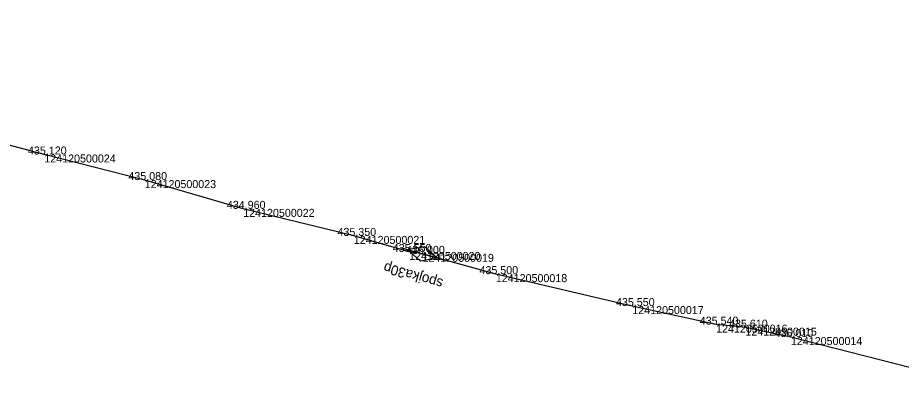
# Model space of a CAD drawing. Extents: x -637342 to -635997, y -1153616 to -1153154.
# Drawn here: x -637005.8 to -636873.3, y -1153373.9 to -1153318.4 of the extents above; entities that cross this region are included whole.
import ezdxf

# ---------------------------------------------------------------- set-up
doc = ezdxf.new("R2010")
doc.units = 0
for name, color, linetype in [('Vrstva 28', 7, 'Continuous'), ('Vrstva 60', 7, 'Continuous'), ('Vrstva 61', 7, 'Continuous')]:
    doc.layers.add(name, color=color, linetype=linetype)

msp = doc.modelspace()

# ---------------------------------------------------------------- linework, layer by layer
at = {"layer": 'Vrstva 28'}
for p, q in [((-636947.36, -1153353.23), (-636944.81, -1153352.76)), ((-636944.81, -1153352.76), (-636942.9, -1153354.53)), ((-636948.48, -1153352.91), (-636941.78, -1153354.85)), ((-636945.45, -1153355), (-636947.36, -1153353.23)), ((-636942.9, -1153354.53), (-636945.45, -1153355))]:
    msp.add_line(p, q, dxfattribs=at)
msp.add_lwpolyline([(-636859.31, -1153373.92), (-636867.59, -1153372.08), (-636889.87, -1153366.37), (-636896.7, -1153364.96), (-636901.09, -1153364.51), (-636913.66, -1153361.72), (-636934.13, -1153356.93), (-636945.13, -1153353.88), (-636947.14, -1153353.6), (-636955.43, -1153351.19), (-636972.02, -1153347.13), (-636986.79, -1153342.81), (-637001.85, -1153338.97), (-637018.07, -1153334.65), (-637042.74, -1153328.68), (-637062.52, -1153323.84), (-637073.89, -1153320.08), (-637082.06, -1153319.38), (-637087.31, -1153318.43)], dxfattribs=at)
at = {"layer": 'Vrstva 60'}
for p, q in [((-637001.85, -1153338.97), (-637001.85, -1153338.97)), ((-636986.79, -1153342.81), (-636986.79, -1153342.81)), ((-636972.02, -1153347.13), (-636972.02, -1153347.13)), ((-636955.43, -1153351.19), (-636955.43, -1153351.19)), ((-636947.14, -1153353.6), (-636947.14, -1153353.6)), ((-636945.13, -1153353.88), (-636945.13, -1153353.88)), ((-636934.13, -1153356.93), (-636934.13, -1153356.93)), ((-636913.66, -1153361.72), (-636913.66, -1153361.72)), ((-636901.09, -1153364.51), (-636901.09, -1153364.51)), ((-636896.7, -1153364.96), (-636896.7, -1153364.96)), ((-636889.87, -1153366.37), (-636889.87, -1153366.37))]:
    msp.add_line(p, q, dxfattribs=at)

# ---------------------------------------------------------------- texts
at = {"layer": 'Vrstva 28'}
msp.add_text('spojka30p', height=1.5, rotation=163.7902, dxfattribs=at).set_placement((-636941.93, -1153357.74))
at = {"layer": 'Vrstva 60'}
for s, p in [('124120500024', (-637001.85, -1153340.17)), ('124120500023', (-636986.79, -1153344.01)), ('124120500022', (-636972.02, -1153348.33)), ('124120500021', (-636955.43, -1153352.39)), ('124120500020', (-636947.14, -1153354.8)), ('124120500019', (-636945.13, -1153355.08)), ('124120500018', (-636934.13, -1153358.13)), ('124120500017', (-636913.66, -1153362.92)), ('124120500016', (-636901.09, -1153365.71)), ('124120500015', (-636896.7, -1153366.16)), ('124120500014', (-636889.87, -1153367.57))]:
    msp.add_text(s, height=1.2, dxfattribs=at).set_placement(p)
at = {"layer": 'Vrstva 61'}
for s, p in [('435.120', (-637004.3, -1153338.97)), ('435.080', (-636989.24, -1153342.81)), ('434.960', (-636974.47, -1153347.13)), ('435.350', (-636957.88, -1153351.19)), ('435.550', (-636949.59, -1153353.6)), ('436.000', (-636947.58, -1153353.88)), ('435.500', (-636936.58, -1153356.93)), ('435.550', (-636916.11, -1153361.72)), ('435.540', (-636903.54, -1153364.51)), ('435.610', (-636899.15, -1153364.96)), ('436.010', (-636892.32, -1153366.37))]:
    msp.add_text(s, height=1.2, dxfattribs=at).set_placement(p)

doc.saveas('drawing.dxf')
